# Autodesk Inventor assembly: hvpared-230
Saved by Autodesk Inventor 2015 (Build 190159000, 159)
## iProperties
Created: 2020-08
Part Number: hvpared-230
Checked By: TraceParts S.A.
Catalog Web Link: www.traceparts.com
Document SubType Name: Assembly
Designer: TraceParts
Company: TraceParts S.A.
Author: TraceParts
REFERENCE: HVPARED-230
DESIGN: HVPARED-230
SUPPLIER: Soler & Palau
TraceParts.PartNumber: 10-04022019-080750
TraceParts.PartTitle: HV-STYLVENT
TraceParts.InstanceId: 10-04022019-080750CSTKUHT8YYNXQ234PUYU943UU
TraceParts.PartStatus: Published
TraceParts.PartVersion: 1.0.1
TRACEPARTS: TRACEPARTS
TraceParts.PartLanguage: en
TraceParts.ClassPath: SOLER_PALAU:10-04022019-080750
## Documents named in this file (4)
- C:\TPO v2\SharedFS\Outgoing\hvpared-230.iam
- C:\TPO v2\SharedFS\Outgoing\hvpared-230_01.ipt
- C:\TPO v2\SharedFS\Outgoing\hvpared-230_02.ipt
- C:\TPO v2\SharedFS\Outgoing\hvpared-230_03.ipt
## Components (3 placed, 3 different names)
1. hvpared-230_01:1
2. hvpared-230_02:1
3. hvpared-230_03:1
